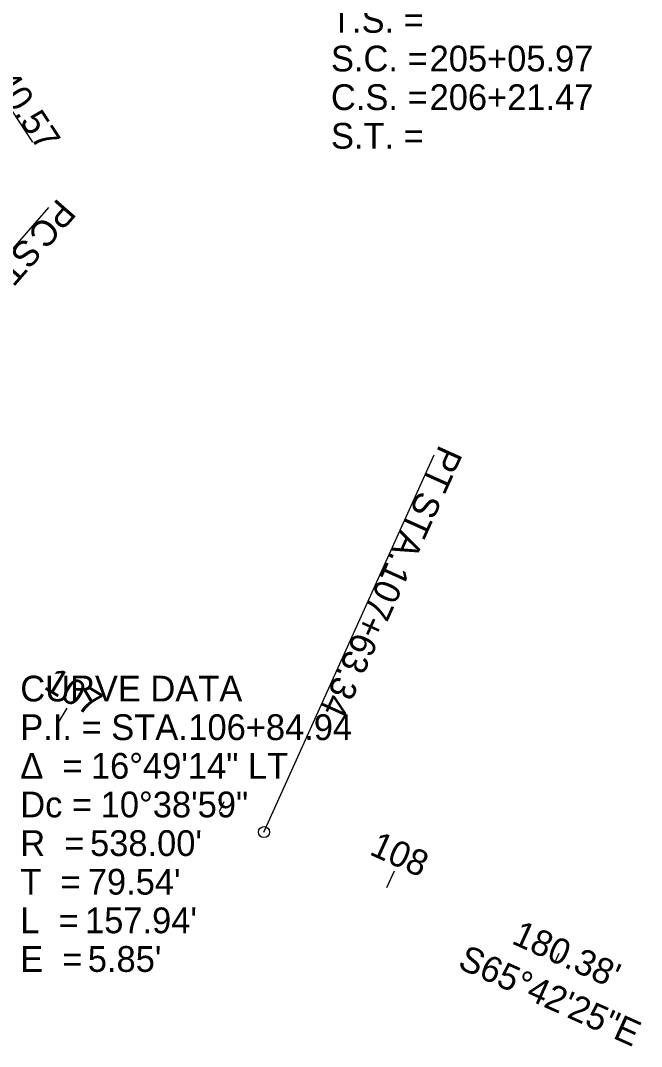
# Model space of a CAD drawing. Extents: x 1598538 to 1602183, y 285823 to 288192.
# Drawn here: x 1601183.3 to 1601352.1, y 286391 to 286669.9 of the extents above; entities that cross this region are included whole.
import ezdxf

# ---------------------------------------------------------------- set-up
doc = ezdxf.new("R2010")
doc.units = 0
for name, color, linetype in [('CM_Corridor_Conceptual', 7, 'Continuous'), ('CM_Corridor_Range_Conceptual', 7, 'Continuous'), ('MD_P_AGB_B', 7, 'Continuous'), ('PV_P_Curb', 7, 'Continuous'), ('PV_P_EOP', 7, 'Continuous')]:
    doc.layers.add(name, color=color, linetype=linetype)

msp = doc.modelspace()

# ---------------------------------------------------------------- linework, layer by layer
at = {"layer": 'MD_P_AGB_B'}
for p, q in [((1601193.41, 286478.68), (1601195.99, 286482.97)), ((1601237.38, 286454.93), (1601238.69, 286457.63)), ((1601282.89, 286434.21), (1601284.95, 286438.77)), ((1601328.46, 286413.64), (1601329.69, 286416.37))]:
    msp.add_line(p, q, dxfattribs=at)
at = {"layer": 'PV_P_Curb'}
for p, q in [((1601124.67, 286730.7), (1601186.62, 286636.79)), ((1601117.05, 286534.32), (1601191.02, 286619.08)), ((1601249.47, 286449.29), (1601295.76, 286551.83))]:
    msp.add_line(p, q, dxfattribs=at)
msp.add_circle((1601249.47, 286449.29), 1.5, dxfattribs=at)

# ---------------------------------------------------------------- texts
at = {"layer": 'CM_Corridor_Conceptual'}
for s, p in [('T.S. = ', (1601267.69, 286666.55)), ('S.C. = ', (1601267.69, 286656.05)), ('205+05.97', (1601294.5, 286656.05)), ('C.S. = ', (1601267.69, 286645.55)), ('206+21.47', (1601294.5, 286645.55)), ('S.T. = ', (1601267.69, 286635.05)), ('CURVE DATA', (1601183.26, 286484.81)), ('P.I. = STA. ', (1601183.26, 286474.31)), ('106+84.94', (1601228.93, 286474.31)), ('Δ  = ', (1601183.26, 286463.81)), ('16°49\'14" LT', (1601202.45, 286463.81)), ('Dc = ', (1601183.26, 286453.31)), ('10°38\'59"', (1601205.11, 286453.31)), ('R  = ', (1601183.26, 286442.81)), ("538.00'", (1601202.22, 286442.81)), ('T  = ', (1601183.26, 286432.31)), ("79.54'", (1601201.61, 286432.31)), ('L  = ', (1601183.26, 286421.81)), ("157.94'", (1601200.86, 286421.81)), ('E  = ', (1601183.26, 286411.31)), ("5.85'", (1601201.61, 286411.31))]:
    msp.add_text(s, height=7, dxfattribs=at).set_placement(p)
at = {"layer": 'CM_Corridor_Range_Conceptual'}
msp.add_text("180.38'", height=7, rotation=335.7068, dxfattribs=at).set_placement((1601316.5, 286419.15))
at = {"layer": 'MD_P_AGB_B'}
for s, rotation, p in [('107', 328.9612, (1601189.31, 286488.44)), ('108', 335.7068, (1601277.86, 286443.34))]:
    msp.add_text(s, height=7, rotation=rotation, dxfattribs=at).set_placement(p)
at = {"layer": 'PV_P_Curb'}
for s, rotation, p in [('207+40.57', 303.4087, (1601164.2, 286670.96)), ('PC', 228.8864, (1601193.55, 286621.82)), (' STA. ', 228.8864, (1601186.01, 286613.18)), ('PT', 245.7068, (1601297.22, 286554.82)), (' STA. ', 245.7068, (1601292.68, 286544.76)), ('107+63.34', 245.7068, (1601282.96, 286523.22))]:
    msp.add_text(s, height=7, rotation=rotation, dxfattribs=at).set_placement(p)
at = {"layer": 'PV_P_EOP'}
msp.add_text('S65°42\'25"E', height=7, rotation=335.7068, dxfattribs=at).set_placement((1601301.82, 286412.5))

doc.saveas('drawing.dxf')
